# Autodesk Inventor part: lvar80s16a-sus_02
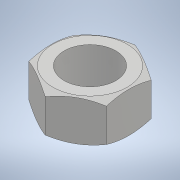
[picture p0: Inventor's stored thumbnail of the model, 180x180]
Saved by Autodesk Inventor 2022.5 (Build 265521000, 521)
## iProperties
Part Number: lvar80s16a-sus_02
Material: 一般
Document SubType Name: Modeling
Designer: ImaoCorp
Density: 1 g/cm^3
Appearance: 既定
Author: ImaoCorp
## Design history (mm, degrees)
feature "lvar80s16a-sus_02"
node "ソリッド1"
